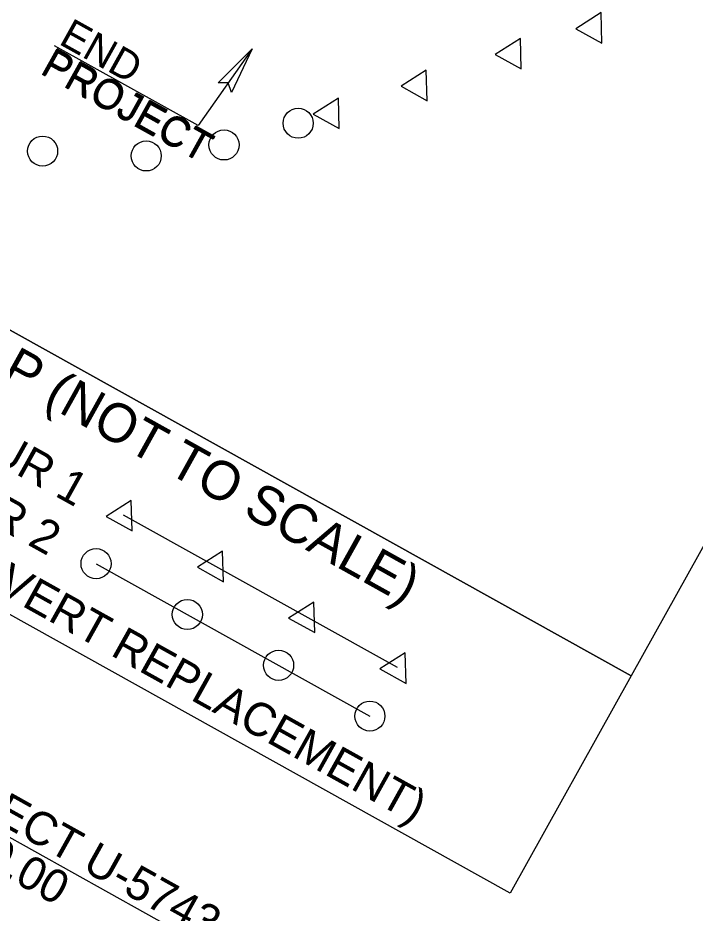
# Model space of a CAD drawing. Extents: x 1754939 to 1770240, y 706534 to 717510.
# Drawn here: x 1762474 to 1763770, y 713316 to 715030 of the extents above; entities that cross this region are included whole.
import ezdxf

# ---------------------------------------------------------------- set-up
doc = ezdxf.new("R2010")
doc.units = 0
for name, color, linetype in [('Prop DSN Text', 7, 'Continuous'), ('Prop Guardrail Anchor Unit CELL', 7, 'Continuous'), ('Prop SS Cut Line', 7, 'Continuous'), ('Scratch_Level_0', 7, 'Continuous'), ('Sheet PE Seal Cell', 7, 'Continuous')]:
    doc.layers.add(name, color=color, linetype=linetype)

msp = doc.modelspace()

# ---------------------------------------------------------------- linework, layer by layer
at = {"layer": 'Prop Guardrail Anchor Unit CELL'}
msp.add_lwpolyline([(1762857.1, 714905.5), (1762922.4, 714970.8), (1762882.8, 714886.7), (1762876.3, 714905.5)], close=True, dxfattribs=at)
at = {"layer": 'Prop SS Cut Line'}
msp.add_line((1761834.8, 713807.6), (1762844, 713245.6), dxfattribs=at)
at = {"layer": 'Scratch_Level_0'}
for p, q in [((1762818.8, 714824), (1762543.9, 714976.1)), ((1762922.4, 714970.8), (1762818.8, 714824))]:
    msp.add_line(p, q, dxfattribs=at)
at = {"layer": 'Sheet PE Seal Cell'}
for p, q in [((1762675.6, 714078.3), (1763199.8, 713786.3)), ((1762623.6, 713984.7), (1763147.8, 713692.8))]:
    msp.add_line(p, q, dxfattribs=at)
for points in [[(1762475.9, 716463.6), (1764515.4, 715327.8), (1763647.8, 713769.9), (1761608.3, 714905.6)], [(1763590.3, 715039.8), (1763542, 715009.1), (1763592, 714981.3)], [(1763435.8, 714990.4), (1763387.5, 714959.8), (1763437.5, 714932)], [(1763255.6, 714929.5), (1763207.4, 714898.8), (1763257.3, 714871)], [(1761608.3, 714905.6), (1763647.8, 713769.9), (1763416.2, 713354), (1761376.7, 714489.7)], [(1763087.6, 714876.2), (1763039.3, 714845.6), (1763089.2, 714817.8)], [(1762691, 714105.9), (1762642.7, 714075.3), (1762692.7, 714047.4)], [(1762865.8, 714008.6), (1762817.5, 713977.9), (1762867.5, 713950.1)], [(1763040.5, 713911.3), (1762992.2, 713880.6), (1763042.2, 713852.8)], [(1763215.2, 713814), (1763166.9, 713783.3), (1763216.9, 713755.5)]]:
    msp.add_lwpolyline(points, close=True, dxfattribs=at)
for centre in [(1763010.5, 714828.1), (1762521.3, 714774.7), (1762868.5, 714786.5), (1762719.6, 714765.4), (1762623.6, 713984.7), (1762798.3, 713887.4), (1762973, 713790.1), (1763147.8, 713692.8)]:
    msp.add_circle(centre, 28.8, dxfattribs=at)

# ---------------------------------------------------------------- texts
at = {"layer": 'Prop DSN Text'}
for s, p in [('END', (1762550.2, 714980.8)), ('PROJECT', (1762516, 714925.3)), ('PROJECT', (1762514.3, 714924))]:
    msp.add_text(s, height=56.9, rotation=330.8877, dxfattribs=at).set_placement(p)
at = {"layer": 'Prop SS Cut Line'}
for s, p in [('BEGIN TIP PROJECT U-5743', (1761837.5, 713820.5)), ('-L- POT Sta. 15+00.00', (1761796.8, 713747.5))]:
    msp.add_text(s, height=63.75, rotation=330.8875, dxfattribs=at).set_placement(p)
at = {"layer": 'Sheet PE Seal Cell'}
for s, height, p in [('VICINITY MAP (NOT TO SCALE)', 74.376, (1761917.2, 714627.9)), ('OFF-SITE DETOUR 1', 63.75, (1761847.5, 714502.6)), ('OFF-SITE DETOUR 2', 63.75, (1761795.4, 714409.1)), ('(DETOUR FOR CULVERT REPLACEMENT)', 63.75, (1761743, 714315.1))]:
    msp.add_text(s, height=height, rotation=330.8877, dxfattribs=at).set_placement(p)

doc.saveas('drawing.dxf')
